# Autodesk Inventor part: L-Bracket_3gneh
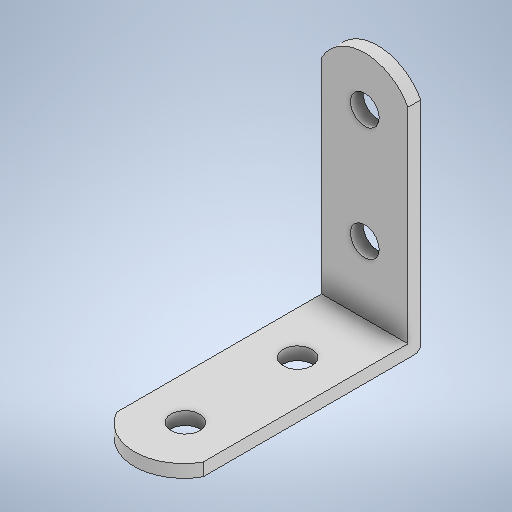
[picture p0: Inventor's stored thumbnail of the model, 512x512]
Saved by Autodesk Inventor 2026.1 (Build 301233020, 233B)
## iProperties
Created: 2026-11
Part Number: L-Bracket_3gneh
Material: Generic
Document SubType Name: Modeling
Designer: hp
Density: 1 g/cm^3
Appearance: Default
Author: hp
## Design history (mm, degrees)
sketch "Sketch1"
  geometry: L1 (0, 0)-(0, 34); L2 (13.5, 34)-(13.5, 0); L3 (0, 0)-(0, 2); L4 (0, 2)-(13.5, 2); L5 (0, 0)-(13.5, 0); C1 r 2.25 at (6.75, 12.5); C2 r 2.25 at (6.75, 30.305); A1 r 7.695 centre (6.75, 30.305) between (13.5, 34) and (0, 34)
  constraints: 10 end point, 3 centre point, 2 point on circle, 2 point on line, 1 coincident, 1 horizontal, 1 perpendicular, 1 vertical
  dimensions: "d0" = 34 distance of L1.start L1.end; "d4" = 4.5 diameter of C1; "d6" = 4.5 diameter of C2
extrude "Extrusion1" new body sketch "Sketch1" distance "d8" = 2; taper "d9" = 0 deg
extrude "Extrusion2" join sketch "Sketch1" distance "d10" = 38; taper "d11" = 0 deg
sketch "Sketch2"
  geometry: L1 (0, 0)-(13.5, 0) reference; L2 (0, 0)-(0, -32); L3 (0, 0)-(0, -36) reference; L4 (13.5, -32)-(13.5, 0); L5 (0, 0)-(13.5, 0); L6 (13.5, -36)-(0, -36) reference; L7 (0, -36)-(13.5, -36); L8 (13.5, -36)-(13.5, -32); C1 r 2.25 at (6.75, -10.5); C2 r 2.25 at (6.75, -28.035); A1 r 7.695 centre (6.75, -28.305) between (0, -32) and (13.5, -32); 2 further points
  constraints: 10 end point, 3 centre point, 2 point on circle, 1 collinear, 1 horizontal, 1 perpendicular, 1 point on line, 1 vertical
  dimensions: "d12" = 32 distance of L1.start L2.end; "d13" = 4.5 diameter of C1; "d14" = 4.5 diameter of C2
extrude "Extrusion3" cut sketch "Sketch2" distance "d15" = 38; taper "d16" = 0 deg
fillet "Fillet1" dims "d17" = 1
body "Solid1"
